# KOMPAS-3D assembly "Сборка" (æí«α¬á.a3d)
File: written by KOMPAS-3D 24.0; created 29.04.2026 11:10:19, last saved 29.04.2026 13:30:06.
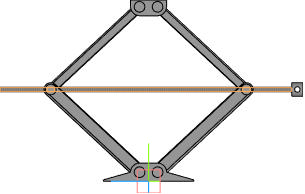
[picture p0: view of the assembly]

Document properties: Автор: USG_411; Полное имя файла: C:\Users\USG_411\Desktop\ИА-2904_411-12\Сборка.a3d

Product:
- Component [detail]: Нижняя платформа  | qty 1  | Масса: 0.370663; Автор: USG_411; source file: Нижняя платформа.m3d
- Component [detail]: Нижняя часть  | qty 2  | Масса: 0.552379; Автор: USG_411; source file: Нижняя часть.m3d
- Component [detail]: Верхняя платформа  | qty 1  | Масса: 0.160905; Автор: USG_411; source file: Верхняя платформа.m3d
- Component [detail]: Верхняя часть  | qty 2  | Масса: 0.236991; Автор: USG_411; source file: Верхняя часть.m3d
- Component [detail]: 12х30  | qty 2  | Масса: 0.023989; Автор: USG_411; source file: 12х30.m3d
- Component [detail]: 12х40  | qty 2  | Масса: 0.032874; Автор: USG_411; source file: 12х40.m3d
- Component [detail]: Фиксатор  | qty 12  | Масса: 0.022657; Автор: USG_411; source file: Фиксатор.m3d
- Component [detail]: 12х25  | qty 2  | Масса: 0.028419; Автор: USG_411; source file: 12х25.m3d
- Component [detail]: Винт  | qty 1  | Масса: 0.510687; Автор: USG_411; source file: Винт.m3d
- Part/product: Сборка
    Масса: 3.063438

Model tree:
1. Эскиз:1  (with: Ребро.Элемент выдавливания:2, Ребро.Элемент выдавливания:1, Грань.Элемент выдавливания:2, Грань.Элемент выдавливания:1, Ребро.Элемент выдавливания:3, Грань.Элемент выдавливания:3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)
     Расстояние = 2; Расстояние = 2; Ориентация = 2; Расстояние = 2; Расстояние = 400; Ориентация = 2; Расстояние = 2; Расстояние = 2; Расстояние = 90; Ориентация = 2

Referenced files in C:\Users\USG_411\Desktop\ИА-2904_411-12\: Нижняя платформа.m3d, Нижняя часть.m3d, Верхняя платформа.m3d, Верхняя часть.m3d, 12х30.m3d, 12х40.m3d, Фиксатор.m3d, 12х25.m3d, Винт.m3d
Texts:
  Точка начала. Х
  Точка начала. Y
  Точка начала. Z
  Нижняя часть (1)
  Нижняя часть (2)
  Верхняя часть (1)
  Верхняя часть (2)
  Фиксатор (1)
  Фиксатор (2)
  Фиксатор (3)
  Фиксатор (4)
  Фиксатор (5)
  Фиксатор (6)
  Фиксатор (7)
  Фиксатор (8)
  Фиксатор (9)
  Фиксатор (10)
  Фиксатор (11)
  Фиксатор (12)
  Плоскость ZY.Начало координат
  Плоскость ZX.Начало координат
  Плоскость XY.Начало координат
